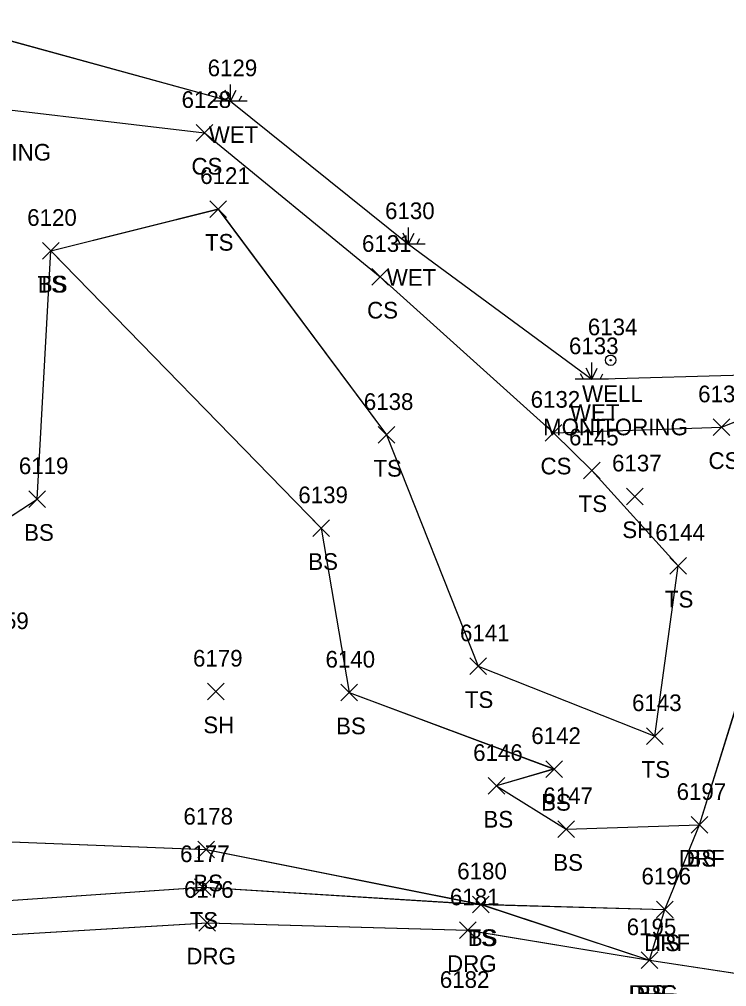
# Model space of a CAD drawing. Extents: x 1554668 to 1563881, y 831386 to 834374.
# Drawn here: x 1562812.5 to 1562897.4, y 833991 to 834107.1 of the extents above; entities that cross this region are included whole.
import ezdxf

# ---------------------------------------------------------------- set-up
doc = ezdxf.new("R2010")
doc.units = 0
for name, color, linetype in [('L_A', 7, 'Continuous'), ('L_I', 7, 'Continuous'), ('L_TIC', 7, 'Continuous'), ('LELB', 7, 'Continuous'), ('LWET', 7, 'Continuous'), ('R_A', 7, 'Continuous'), ('R_I', 7, 'Continuous'), ('R_TIC', 7, 'Continuous'), ('RDF', 7, 'Continuous'), ('RDG', 7, 'Continuous'), ('U_A', 7, 'Continuous'), ('U_C', 7, 'Continuous'), ('U_I', 7, 'Continuous'), ('UWW', 7, 'Continuous')]:
    doc.layers.add(name, color=color, linetype=linetype)

msp = doc.modelspace()

# ---------------------------------------------------------------- linework, layer by layer
at = {"layer": 'L_TIC'}
for points in [[(1562833.72, 834092.43), (1562835.72, 834094.43)], [(1562835.72, 834092.43), (1562833.72, 834094.43)], [(1562835.38, 834083.3), (1562837.38, 834085.3)], [(1562837.38, 834083.3), (1562835.38, 834085.3)], [(1562815.28, 834078.28), (1562817.28, 834080.28)], [(1562817.28, 834078.28), (1562815.28, 834080.28)], [(1562815.28, 834078.28), (1562817.28, 834080.28)], [(1562817.28, 834078.28), (1562815.28, 834080.28)], [(1562854.8, 834075.16), (1562856.8, 834077.16)], [(1562856.8, 834075.16), (1562854.8, 834077.16)], [(1562895.77, 834057.11), (1562897.77, 834059.11)], [(1562897.77, 834057.11), (1562895.77, 834059.11)], [(1562855.59, 834056.19), (1562857.59, 834058.19)], [(1562857.59, 834056.19), (1562855.59, 834058.19)], [(1562875.61, 834056.46), (1562877.61, 834058.46)], [(1562877.61, 834056.46), (1562875.61, 834058.46)], [(1562880.22, 834051.94), (1562882.22, 834053.94)], [(1562882.22, 834051.94), (1562880.22, 834053.94)], [(1562885.38, 834048.82), (1562887.38, 834050.82)], [(1562887.38, 834048.82), (1562885.38, 834050.82)], [(1562813.64, 834048.49), (1562815.64, 834050.49)], [(1562815.64, 834048.49), (1562813.64, 834050.49)], [(1562847.74, 834045), (1562849.74, 834047)], [(1562849.74, 834045), (1562847.74, 834047)], [(1562890.57, 834040.49), (1562892.57, 834042.49)], [(1562892.57, 834040.49), (1562890.57, 834042.49)], [(1562866.56, 834028.44), (1562868.56, 834030.44)], [(1562868.56, 834028.44), (1562866.56, 834030.44)], [(1562835.1, 834025.4), (1562837.1, 834027.4)], [(1562837.1, 834025.4), (1562835.1, 834027.4)], [(1562851.08, 834025.28), (1562853.08, 834027.28)], [(1562853.08, 834025.28), (1562851.08, 834027.28)], [(1562887.78, 834020.06), (1562889.78, 834022.06)], [(1562889.78, 834020.06), (1562887.78, 834022.06)], [(1562875.69, 834016.11), (1562877.69, 834018.11)], [(1562877.69, 834016.11), (1562875.69, 834018.11)], [(1562868.77, 834014.08), (1562870.77, 834016.08)], [(1562870.77, 834014.08), (1562868.77, 834016.08)], [(1562893.13, 834009.4), (1562895.13, 834011.4)], [(1562895.13, 834009.4), (1562893.13, 834011.4)], [(1562877.13, 834008.9), (1562879.13, 834010.9)], [(1562879.13, 834008.9), (1562877.13, 834010.9)], [(1562833.94, 834006.44), (1562835.94, 834008.44)], [(1562835.94, 834006.44), (1562833.94, 834008.44)], [(1562833.54, 834001.94), (1562835.54, 834003.94)], [(1562835.54, 834001.94), (1562833.54, 834003.94)], [(1562866.88, 833999.87), (1562868.88, 834001.87)], [(1562868.88, 833999.87), (1562866.88, 834001.87)], [(1562866.88, 833999.87), (1562868.88, 834001.87)], [(1562868.88, 833999.87), (1562866.88, 834001.87)], [(1562888.96, 833999.26), (1562890.96, 834001.26)], [(1562890.96, 833999.26), (1562888.96, 834001.26)], [(1562887.14, 833993.17), (1562889.14, 833995.17)], [(1562889.14, 833993.17), (1562887.14, 833995.17)]]:
    msp.add_lwpolyline(points, dxfattribs=at)
at = {"layer": 'LELB'}
for points in [[(1562755.62, 834102.97), (1562772.83, 834101.63), (1562800.07, 834097.51), (1562834.72, 834093.43), (1562855.8, 834076.16), (1562876.61, 834057.46), (1562896.77, 834058.11), (1562903.58, 834060.82), (1562909.29, 834059.09)], [(1562755.63, 834102.98), (1562772.84, 834101.64), (1562800.07, 834097.51), (1562834.73, 834093.43), (1562855.81, 834076.17), (1562876.61, 834057.46), (1562896.77, 834058.12), (1562903.59, 834060.83), (1562909.29, 834059.09)], [(1562755.63, 834102.98), (1562772.84, 834101.64), (1562800.07, 834097.51), (1562834.73, 834093.43), (1562855.81, 834076.17), (1562876.61, 834057.46), (1562896.77, 834058.12), (1562903.59, 834060.83), (1562909.29, 834059.09)], [(1562755.63, 834102.98), (1562772.84, 834101.64), (1562800.07, 834097.51), (1562834.73, 834093.43), (1562855.81, 834076.17), (1562876.61, 834057.46), (1562896.77, 834058.12), (1562903.59, 834060.83), (1562909.29, 834059.09)], [(1562816.28, 834079.29), (1562836.38, 834084.31), (1562856.59, 834057.2), (1562867.57, 834029.45), (1562888.79, 834021.07), (1562891.58, 834041.5), (1562881.23, 834052.94)], [(1562816.28, 834079.29), (1562836.38, 834084.31), (1562856.59, 834057.2), (1562867.57, 834029.45), (1562888.79, 834021.07), (1562891.58, 834041.5), (1562881.23, 834052.94)], [(1562816.28, 834079.29), (1562836.38, 834084.31), (1562856.59, 834057.2), (1562867.57, 834029.45), (1562888.79, 834021.07), (1562891.58, 834041.5), (1562881.23, 834052.94)], [(1562816.28, 834079.28), (1562836.38, 834084.3), (1562856.59, 834057.19), (1562867.56, 834029.44), (1562888.78, 834021.06), (1562891.57, 834041.49), (1562881.22, 834052.94)], [(1562691.51, 834009.05), (1562716.27, 834013.16), (1562733.24, 834028.19), (1562750.45, 834030.96), (1562771.37, 834029.54), (1562790.47, 834033.76), (1562814.64, 834049.5), (1562816.28, 834079.29), (1562848.74, 834046), (1562852.08, 834026.29), (1562876.69, 834017.12), (1562869.77, 834015.08), (1562878.14, 834009.91), (1562894.13, 834010.41)], [(1562691.51, 834009.05), (1562716.27, 834013.16), (1562733.24, 834028.19), (1562750.45, 834030.96), (1562771.37, 834029.54), (1562790.47, 834033.76), (1562814.64, 834049.5), (1562816.28, 834079.29), (1562848.74, 834046), (1562852.08, 834026.29), (1562876.69, 834017.12), (1562869.77, 834015.08), (1562878.14, 834009.91), (1562894.13, 834010.41)], [(1562691.51, 834009.05), (1562716.27, 834013.16), (1562733.24, 834028.19), (1562750.45, 834030.96), (1562771.37, 834029.54), (1562790.47, 834033.76), (1562814.64, 834049.5), (1562816.28, 834079.29), (1562848.74, 834046), (1562852.08, 834026.29), (1562876.69, 834017.12), (1562869.77, 834015.08), (1562878.14, 834009.91), (1562894.13, 834010.41)], [(1562691.52, 834009.05), (1562716.26, 834013.15), (1562733.23, 834028.18), (1562750.44, 834030.95), (1562771.37, 834029.53), (1562790.47, 834033.75), (1562814.64, 834049.49), (1562816.28, 834079.28), (1562848.74, 834046), (1562852.08, 834026.28), (1562876.69, 834017.11), (1562869.77, 834015.08), (1562878.13, 834009.9), (1562894.13, 834010.4)], [(1562881.23, 834052.94), (1562876.61, 834057.46)], [(1562881.23, 834052.94), (1562876.61, 834057.46)], [(1562881.23, 834052.94), (1562876.61, 834057.46)], [(1562881.22, 834052.94), (1562876.61, 834057.46)], [(1562776.88, 834001.53), (1562799.34, 834008.87), (1562834.94, 834007.44), (1562867.88, 834000.87), (1562888.14, 833994.17)], [(1562776.89, 834001.54), (1562799.34, 834008.87), (1562834.95, 834007.45), (1562867.89, 834000.88), (1562888.15, 833994.18)], [(1562776.89, 834001.54), (1562799.34, 834008.87), (1562834.95, 834007.45), (1562867.89, 834000.88), (1562888.15, 833994.18)], [(1562776.89, 834001.54), (1562799.34, 834008.87), (1562834.95, 834007.45), (1562867.89, 834000.88), (1562888.15, 833994.18)], [(1562650.42, 833999.03), (1562630.69, 833991.64), (1562633.83, 833982.26), (1562644.5, 833981.3), (1562656.86, 833987.17), (1562679, 833981.55), (1562709.13, 833986.31), (1562743.64, 833992.83), (1562777.2, 833999.05), (1562799.43, 834000.54), (1562834.55, 834002.95), (1562867.89, 834000.88), (1562889.96, 834000.26)], [(1562650.42, 833999.03), (1562630.69, 833991.64), (1562633.83, 833982.26), (1562644.5, 833981.3), (1562656.86, 833987.17), (1562679, 833981.55), (1562709.13, 833986.31), (1562743.64, 833992.83), (1562777.2, 833999.05), (1562799.43, 834000.54), (1562834.55, 834002.95), (1562867.89, 834000.88), (1562889.96, 834000.26)], [(1562650.42, 833999.03), (1562630.69, 833991.64), (1562633.83, 833982.26), (1562644.5, 833981.3), (1562656.86, 833987.17), (1562679, 833981.55), (1562709.13, 833986.31), (1562743.64, 833992.83), (1562777.2, 833999.05), (1562799.43, 834000.54), (1562834.55, 834002.95), (1562867.89, 834000.88), (1562889.96, 834000.26)], [(1562650.42, 833999.02), (1562630.68, 833991.63), (1562633.83, 833982.25), (1562644.5, 833981.29), (1562656.86, 833987.17), (1562679, 833981.54), (1562709.13, 833986.3), (1562743.63, 833992.82), (1562777.19, 833999.04), (1562799.43, 834000.53), (1562834.54, 834002.94), (1562867.88, 834000.87), (1562889.96, 834000.26)]]:
    msp.add_lwpolyline(points, dxfattribs=at)
at = {"layer": 'LWET'}
for p, q in [((1562837.86, 834097.23), (1562837.19, 834098.56)), ((1562837.86, 834097.23), (1562837.86, 834099.23)), ((1562837.86, 834097.23), (1562838.52, 834098.56)), ((1562839.86, 834097.23), (1562835.86, 834097.23)), ((1562836.86, 834097.23), (1562836.52, 834097.89)), ((1562838.86, 834097.23), (1562839.19, 834097.89)), ((1562859.22, 834080.09), (1562859.22, 834082.09)), ((1562858.22, 834080.09), (1562857.89, 834080.75)), ((1562859.22, 834080.09), (1562858.56, 834081.42)), ((1562859.22, 834080.09), (1562859.89, 834081.42)), ((1562860.22, 834080.09), (1562860.56, 834080.75)), ((1562861.22, 834080.09), (1562857.22, 834080.09)), ((1562881.21, 834063.88), (1562881.21, 834065.88)), ((1562880.21, 834063.88), (1562879.87, 834064.54)), ((1562881.21, 834063.88), (1562880.54, 834065.21)), ((1562881.21, 834063.88), (1562881.87, 834065.21)), ((1562882.21, 834063.88), (1562882.54, 834064.54)), ((1562883.21, 834063.88), (1562879.21, 834063.88))]:
    msp.add_line(p, q, dxfattribs=at)
for points in [[(1562772.83, 834101.63), (1562802.03, 834107.05), (1562837.86, 834097.23), (1562859.22, 834080.09), (1562881.21, 834063.88), (1562900.95, 834064.44), (1562904.98, 834063.35), (1562910.61, 834063.22), (1562910.29, 834065.83), (1562905.72, 834075.23)], [(1562772.84, 834101.64), (1562802.03, 834107.06), (1562837.86, 834097.23), (1562859.23, 834080.09), (1562881.21, 834063.89), (1562900.95, 834064.44), (1562904.99, 834063.36), (1562910.62, 834063.23), (1562910.3, 834065.84), (1562905.72, 834075.24)], [(1562772.84, 834101.64), (1562802.03, 834107.06), (1562837.86, 834097.23), (1562859.23, 834080.09), (1562881.21, 834063.89), (1562900.95, 834064.44), (1562904.99, 834063.36), (1562910.62, 834063.23), (1562910.3, 834065.84), (1562905.72, 834075.24)], [(1562772.84, 834101.64), (1562802.03, 834107.06), (1562837.86, 834097.23), (1562859.23, 834080.09), (1562881.21, 834063.89), (1562900.95, 834064.44), (1562904.99, 834063.36), (1562910.62, 834063.23), (1562910.3, 834065.84), (1562905.72, 834075.24)]]:
    msp.add_lwpolyline(points, dxfattribs=at)
at = {"layer": 'R_TIC'}
for points in [[(1562893.13, 834009.4), (1562895.13, 834011.4)], [(1562895.13, 834009.4), (1562893.13, 834011.4)], [(1562888.96, 833999.26), (1562890.96, 834001.26)], [(1562890.96, 833999.26), (1562888.96, 834001.26)], [(1562834.06, 833997.66), (1562836.06, 833999.66)], [(1562836.06, 833997.66), (1562834.06, 833999.66)], [(1562865.35, 833996.76), (1562867.35, 833998.76)], [(1562867.35, 833996.76), (1562865.35, 833998.76)], [(1562887.14, 833993.17), (1562889.14, 833995.17)], [(1562889.14, 833993.17), (1562887.14, 833995.17)], [(1562887.14, 833993.17), (1562889.14, 833995.17)], [(1562889.14, 833993.17), (1562887.14, 833995.17)]]:
    msp.add_lwpolyline(points, dxfattribs=at)
at = {"layer": 'RDF'}
for points in [[(1562888.14, 833994.17), (1562889.96, 834000.26), (1562894.13, 834010.4), (1562900.07, 834029.5), (1562906.59, 834048.21), (1562909.29, 834059.09), (1562911.75, 834066.21), (1562914.57, 834075.39)], [(1562888.15, 833994.18), (1562889.96, 834000.26), (1562894.13, 834010.41), (1562900.08, 834029.5), (1562906.59, 834048.22), (1562909.29, 834059.09), (1562911.75, 834066.22), (1562914.57, 834075.39)], [(1562888.15, 833994.18), (1562889.96, 834000.26), (1562894.13, 834010.41), (1562900.08, 834029.5), (1562906.59, 834048.22), (1562909.29, 834059.09), (1562911.75, 834066.22), (1562914.57, 834075.39)], [(1562888.15, 833994.18), (1562889.96, 834000.26), (1562894.13, 834010.41), (1562900.08, 834029.5), (1562906.59, 834048.22), (1562909.29, 834059.09), (1562911.75, 834066.22), (1562914.57, 834075.39)]]:
    msp.add_lwpolyline(points, dxfattribs=at)
at = {"layer": 'RDG'}
for points in [[(1562664.46, 833963.52), (1562679.57, 833968.96), (1562709.28, 833980.66), (1562744.55, 833992.05), (1562773.88, 833995.67), (1562799.45, 833996.54), (1562835.06, 833998.66), (1562866.35, 833997.76), (1562888.14, 833994.17), (1562902.59, 833991.96), (1562920.83, 833987.33), (1562917.32, 833974.5)], [(1562664.47, 833963.54), (1562679.57, 833968.96), (1562709.28, 833980.67), (1562744.55, 833992.05), (1562773.89, 833995.68), (1562799.46, 833996.55), (1562835.07, 833998.67), (1562866.36, 833997.77), (1562888.15, 833994.18), (1562902.6, 833991.97), (1562920.84, 833987.33), (1562917.32, 833974.51)], [(1562664.47, 833963.54), (1562679.57, 833968.96), (1562709.28, 833980.67), (1562744.55, 833992.05), (1562773.89, 833995.68), (1562799.46, 833996.55), (1562835.07, 833998.67), (1562866.36, 833997.77), (1562888.15, 833994.18), (1562902.6, 833991.97), (1562920.84, 833987.33), (1562917.32, 833974.51)], [(1562664.47, 833963.54), (1562679.57, 833968.96), (1562709.28, 833980.67), (1562744.55, 833992.05), (1562773.89, 833995.68), (1562799.46, 833996.55), (1562835.07, 833998.67), (1562866.36, 833997.77), (1562888.15, 833994.18), (1562902.6, 833991.97), (1562920.84, 833987.33), (1562917.32, 833974.51)]]:
    msp.add_lwpolyline(points, dxfattribs=at)
at = {"layer": 'UWW'}
for radius in [0.625, 0.0833]:
    msp.add_circle((1562883.47, 834066.15), radius, dxfattribs=at)

# ---------------------------------------------------------------- texts
at = {"layer": 'L_A'}
for s, p in [('WET', (1562835.24, 834092.23)), ('CS', (1562833.16, 834088.43)), ('TS', (1562834.79, 834079.3)), ('TS', (1562814.69, 834074.28)), ('BS', (1562814.72, 834074.28)), ('WET', (1562856.6, 834075.09)), ('CS', (1562854.24, 834071.16)), ('WET', (1562878.58, 834058.88)), ('TS', (1562855, 834052.19)), ('CS', (1562875.05, 834052.46)), ('CS', (1562895.21, 834053.11)), ('TS', (1562879.63, 834047.94)), ('BS', (1562813.08, 834044.49)), ('SH', (1562884.87, 834044.82)), ('BS', (1562847.18, 834041)), ('TS', (1562889.98, 834036.49)), ('TS', (1562865.97, 834024.44)), ('SH', (1562834.59, 834021.4)), ('BS', (1562850.52, 834021.28)), ('TS', (1562887.19, 834016.06)), ('BS', (1562875.13, 834012.11)), ('BS', (1562868.21, 834010.08)), ('BS', (1562876.58, 834004.9)), ('BS', (1562892.57, 834005.4)), ('BS', (1562833.39, 834002.44)), ('TS', (1562832.95, 833997.94)), ('TS', (1562866.29, 833995.87)), ('BS', (1562866.32, 833995.87)), ('TS', (1562888.37, 833995.26)), ('BS', (1562886.58, 833989.17))]:
    msp.add_text(s, height=2, dxfattribs=at).set_placement(p)
at = {"layer": 'L_I'}
for s, p in [('6129', (1562835.11, 834100.23)), ('6128', (1562831.98, 834096.43)), ('6121', (1562834.21, 834087.3)), ('6120', (1562813.45, 834082.28)), ('6120', (1562813.45, 834082.28)), ('6130', (1562856.4, 834083.09)), ('6131', (1562853.63, 834079.16)), ('6133', (1562878.47, 834066.88)), ('6138', (1562853.85, 834060.19)), ('6132', (1562873.87, 834060.46)), ('6136', (1562893.97, 834061.11)), ('6145', (1562878.48, 834055.94)), ('6119', (1562812.45, 834052.49)), ('6137', (1562883.64, 834052.82)), ('6139', (1562845.99, 834049)), ('6144', (1562888.83, 834044.49)), ('6159', (1562807.69, 834033.9)), ('6141', (1562865.39, 834032.44)), ('6179', (1562833.35, 834029.4)), ('6140', (1562849.25, 834029.28)), ('6143', (1562886.04, 834024.06)), ('6142', (1562873.95, 834020.11)), ('6146', (1562866.97, 834018.08)), ('6147', (1562875.39, 834012.9)), ('6197', (1562891.39, 834013.4)), ('6178', (1562832.2, 834010.44)), ('6177', (1562831.8, 834005.94)), ('6180', (1562865.06, 834003.87)), ('6180', (1562865.06, 834003.87)), ('6196', (1562887.17, 834003.26)), ('6195', (1562885.4, 833997.17))]:
    msp.add_text(s, height=2, dxfattribs=at).set_placement(p)
at = {"layer": 'R_A'}
for s, p in [('DRF', (1562891.66, 834005.4)), ('DRF', (1562887.5, 833995.26)), ('DRG', (1562832.55, 833993.66)), ('DRG', (1562863.84, 833992.76)), ('DRG', (1562885.63, 833989.17)), ('DRF', (1562885.68, 833989.17))]:
    msp.add_text(s, height=2, dxfattribs=at).set_placement(p)
at = {"layer": 'R_I'}
for s, p in [('6197', (1562891.39, 834013.4)), ('6196', (1562887.17, 834003.26)), ('6176', (1562832.27, 834001.66)), ('6181', (1562864.18, 834000.76)), ('6195', (1562885.4, 833997.17)), ('6195', (1562885.4, 833997.17)), ('6182', (1562862.97, 833990.85))]:
    msp.add_text(s, height=2, dxfattribs=at).set_placement(p)
at = {"layer": 'U_A'}
msp.add_text('WELL', height=2, dxfattribs=at).set_placement((1562880.04, 834061.15))
at = {"layer": 'U_C'}
for p in [(1562798.93, 834090.11), (1562875.36, 834057.15)]:
    msp.add_text('MONITORING', height=2, dxfattribs=at).set_placement(p)
at = {"layer": 'U_I'}
msp.add_text('6134', height=2, dxfattribs=at).set_placement((1562880.73, 834069.15))

doc.saveas('drawing.dxf')
